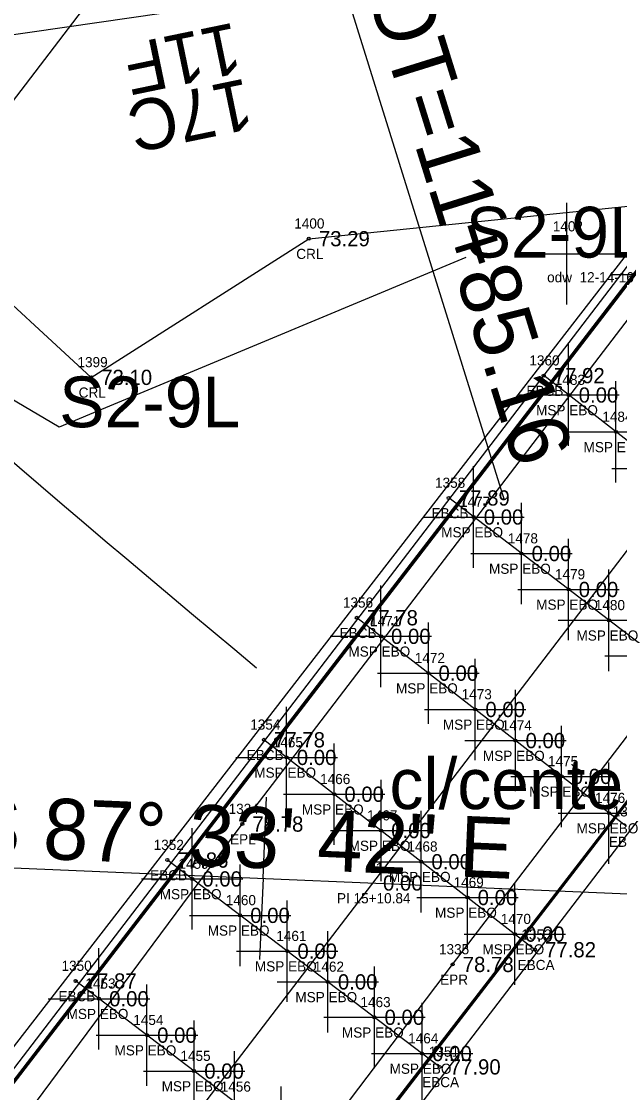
# Model space of a CAD drawing. Extents: x 2500794 to 2511032, y 910653 to 917533.
# Drawn here: x 2506040.7 to 2506099.6, y 913842.2 to 913947.8 of the extents above; entities that cross this region are included whole.
import ezdxf

# ---------------------------------------------------------------- set-up
doc = ezdxf.new("R2010")
doc.units = 0
for name, color, linetype in [('Default', 7, 'Continuous'), ('RD_EX_BldgApp', 7, 'Continuous'), ('RD_EX_Bridge', 7, 'Continuous'), ('RD_EX_Bridge_txCode', 7, 'Continuous'), ('RD_EX_GuardRail', 7, 'Continuous'), ('RD_EX_H2O', 7, 'Continuous'), ('RD_EX_H2O_txCode', 7, 'Continuous'), ('RD_EX_Misc', 7, 'Continuous'), ('RD_EX_Misc_txCode', 7, 'Continuous'), ('RD_EX_Road', 7, 'Continuous'), ('RD_EX_Road_txCode', 7, 'Continuous'), ('RD_EX_RW', 7, 'Continuous'), ('RD_EX_TX_Bridge_ELEV', 7, 'Continuous'), ('RD_EX_TX_H2O_ELEV', 7, 'Continuous'), ('RD_EX_TX_Misc_ELEV', 7, 'Continuous'), ('RD_EX_TX_Road_ELEV', 7, 'Continuous'), ('RD_EX_Wall', 7, 'Continuous'), ('RD_HC_Cl', 7, 'Continuous'), ('RD_HC_Data', 7, 'Continuous'), ('RD_HC_Data_Tic', 7, 'Continuous'), ('RD_HC_Survey_ELEV', 7, 'Continuous'), ('RD_HC_txCode', 7, 'Continuous'), ('RD_PD_Bridge', 7, 'Continuous'), ('RD_PD_Detour', 7, 'Continuous'), ('RD_PD_Signals', 7, 'Continuous'), ('RD_SMD_Locator', 7, 'Continuous')]:
    doc.layers.add(name, color=color, linetype=linetype)

# ---------------------------------------------------------------- blocks, each defined once
blk = doc.blocks.new('POINT_DISPLAY')
at = {"layer": 'Default'}
blk.add_line((0, 0), (0, 0), dxfattribs=at)
blk = doc.blocks.new('Non-Wetland Waters (Tributaries)')
at = {"layer": 'Default'}
blk.add_lwpolyline([(636545.457, 232136.839), (636535.278, 232132.59), (636524.99, 232138.661), (636521.558, 232134.094), (636513.303, 232133.696), (636494.497, 232132.445), (636478.322, 232133.569), (636463.424, 232143.109), (636451.693, 232146.366), (636448.31, 232143.99)], dxfattribs=at)

msp = doc.modelspace()

# ---------------------------------------------------------------- linework, layer by layer
at = {"layer": 'RD_EX_BldgApp'}
msp.add_line((2506016.51, 913816.53), (2506110.72, 913938.26), dxfattribs=at)
at = {"layer": 'RD_EX_Bridge'}
for p, q in [((2506118.69, 913892.22), (2506092.16, 913912.92)), ((2506109.65, 913880.37), (2506082.8, 913900.86)), ((2506100.31, 913868.46), (2506073.74, 913889.05)), ((2506091.3, 913856.32), (2506064.58, 913877.02)), ((2506081.9, 913844.77), (2506055.06, 913865.16)), ((2506072.88, 913832.83), (2506046.02, 913853.24))]:
    msp.add_line(p, q, dxfattribs=at)
for points in [[(2506044.21, 913797.79), (2506019.43, 913816.8), (2506111, 913935.92), (2506135.82, 913916.84), (2506044.21, 913797.79)], [(2506111.24, 913935.99), (2506135.76, 913916.92), (2506044.08, 913798.01), (2506019.65, 913816.86), (2506111.24, 913935.99)]]:
    msp.add_lwpolyline(points, dxfattribs=at)
at = {"layer": 'RD_EX_GuardRail'}
for p, q in [((2506019.73, 913816.87), (2506111.18, 913935.82)), ((2506044.2, 913797.96), (2506135.82, 913916.84))]:
    msp.add_line(p, q, dxfattribs=at)
at = {"layer": 'RD_EX_H2O_txCode'}
msp.add_lwpolyline([(2505808.2, 913925.07), (2505825.64, 913915.36), (2505914.54, 913915.98), (2505996.26, 913926.38), (2506005.4, 913936.74), (2506012.64, 913937.08), (2506022.61, 913935.73), (2506047.54, 913912.75), (2506069, 913926.42), (2506101.76, 913929.76), (2506134.82, 913911.49), (2506168.31, 913924.14), (2506205.52, 913926.29), (2506300.04, 913899.96), (2506387.24, 913834.45), (2506403.62, 913708.7), (2506351.33, 913635.45), (2506287.73, 913577.34)], dxfattribs=at)
at = {"layer": 'RD_EX_Misc'}
for p, q in [((2506094.44, 913919.94), (2506094.44, 913929.94)), ((2506089.44, 913924.94), (2506099.44, 913924.94)), ((2506098.84, 913922.89), (2506108.84, 913922.89)), ((2506094.61, 913906.01), (2506094.61, 913916.01)), ((2506099.28, 913902.37), (2506099.28, 913912.37)), ((2506089.61, 913911.01), (2506099.61, 913911.01)), ((2506094.28, 913907.37), (2506104.28, 913907.37)), ((2506085.25, 913893.98), (2506085.25, 913903.98)), ((2506098.89, 913903.77), (2506108.89, 913903.77)), ((2506089.97, 913890.38), (2506089.97, 913900.38)), ((2506080.25, 913898.98), (2506090.25, 913898.98)), ((2506094.61, 913886.84), (2506094.61, 913896.84)), ((2506084.97, 913895.38), (2506094.97, 913895.38)), ((2506098.59, 913883.8), (2506098.59, 913893.8)), ((2506076.11, 913882.22), (2506076.11, 913892.22)), ((2506089.61, 913891.84), (2506099.61, 913891.84)), ((2506080.79, 913878.59), (2506080.79, 913888.59)), ((2506093.59, 913888.8), (2506103.59, 913888.8)), ((2506071.11, 913887.22), (2506081.11, 913887.22)), ((2506085.41, 913875.01), (2506085.41, 913885.01)), ((2506098.18, 913885.3), (2506108.18, 913885.3)), ((2506075.79, 913883.59), (2506085.79, 913883.59)), ((2506089.37, 913871.94), (2506089.37, 913881.94)), ((2506066.82, 913870.28), (2506066.82, 913880.28)), ((2506080.41, 913880.01), (2506090.41, 913880.01)), ((2506093.93, 913868.41), (2506093.93, 913878.41)), ((2506071.51, 913866.65), (2506071.51, 913876.65)), ((2506084.37, 913876.94), (2506094.37, 913876.94)), ((2506061.82, 913875.28), (2506071.82, 913875.28)), ((2506098.59, 913864.79), (2506098.59, 913874.79)), ((2506088.93, 913873.41), (2506098.93, 913873.41)), ((2506076.13, 913863.07), (2506076.13, 913873.07)), ((2506066.51, 913871.65), (2506076.51, 913871.65)), ((2506080.09, 913860), (2506080.09, 913870)), ((2506093.59, 913869.79), (2506103.59, 913869.79)), ((2506057.51, 913858.3), (2506057.51, 913868.3)), ((2506071.13, 913868.07), (2506081.13, 913868.07)), ((2506084.65, 913856.47), (2506084.65, 913866.47)), ((2506075.09, 913865), (2506085.09, 913865)), ((2506062.23, 913854.71), (2506062.23, 913864.71)), ((2506052.51, 913863.3), (2506062.51, 913863.3)), ((2506089.32, 913852.86), (2506089.32, 913862.86)), ((2506066.88, 913851.18), (2506066.88, 913861.18)), ((2506079.65, 913861.47), (2506089.65, 913861.47)), ((2506057.23, 913859.71), (2506067.23, 913859.71)), ((2506070.87, 913848.15), (2506070.87, 913858.15)), ((2506084.32, 913857.86), (2506094.32, 913857.86)), ((2506048.32, 913846.49), (2506048.32, 913856.49)), ((2506061.88, 913856.18), (2506071.88, 913856.18)), ((2506075.47, 913844.66), (2506075.47, 913854.66)), ((2506065.87, 913853.15), (2506075.87, 913853.15)), ((2506053.05, 913842.9), (2506053.05, 913852.9)), ((2506043.32, 913851.49), (2506053.32, 913851.49)), ((2506080.17, 913841.09), (2506080.17, 913851.09)), ((2506057.7, 913839.36), (2506057.7, 913849.36)), ((2506070.47, 913849.66), (2506080.47, 913849.66)), ((2506048.05, 913847.9), (2506058.05, 913847.9)), ((2506061.69, 913836.33), (2506061.69, 913846.33)), ((2506075.17, 913846.09), (2506085.17, 913846.09)), ((2506052.7, 913844.36), (2506062.7, 913844.36)), ((2506066.28, 913832.84), (2506066.28, 913842.84))]:
    msp.add_line(p, q, dxfattribs=at)
at = {"layer": 'RD_EX_Road'}
for points in [[(2506022.41, 913814.76), (2506062.45, 913868.71), (2506112.78, 913934.56)], [(2506041.83, 913800.29), (2506083.18, 913854.87), (2506132.58, 913919.43)]]:
    msp.add_lwpolyline(points, dxfattribs=at)
at = {"layer": 'RD_EX_RW'}
msp.add_line((2505954.67, 913828.58), (2506112.58, 914035.13), dxfattribs=at)
at = {"layer": 'RD_EX_Wall'}
msp.add_arc((2507719.02, 915869.8), 2585.05, 222.30098, 230.18686, dxfattribs=at)
at = {"layer": 'RD_HC_Cl'}
for p, q in [((2505807.57, 913512.69), (2506748.89, 914743.92)), ((2505870.76, 913871.61), (2506259.06, 913855.07))]:
    msp.add_line(p, q, dxfattribs=at)
at = {"layer": 'RD_HC_Data'}
msp.add_line((2506051.85, 914017.46), (2506088.25, 913900.68), dxfattribs=at)
at = {"layer": 'RD_HC_Data_Tic'}
for q in [(2506064.83, 913871.35), (2506064.15, 913855.37)]:
    msp.add_line((2506064.49, 913863.36), q, dxfattribs=at)
at = {"layer": 'RD_PD_Bridge'}
for p, q in [((2506007.09, 913801.65), (2506128.56, 913960.53)), ((2506034.1, 913781), (2506155.57, 913939.88))]:
    msp.add_line(p, q, dxfattribs=at)
at = {"layer": 'RD_PD_Signals'}
msp.add_line((2506061.31, 913949.6), (2506006.44, 913941.72), dxfattribs=at)
at = {"layer": 'RD_SMD_Locator'}
for centre in [(2506069, 913926.42), (2506047.54, 913912.75), (2506092.16, 913912.92), (2506094.61, 913911.01), (2506099.28, 913907.37), (2506082.8, 913900.86), (2506085.25, 913898.98), (2506089.97, 913895.38), (2506094.61, 913891.84), (2506073.74, 913889.05), (2506098.59, 913888.8), (2506076.11, 913887.22), (2506080.79, 913883.59), (2506085.41, 913880.01), (2506064.58, 913877.02), (2506089.37, 913876.94), (2506066.82, 913875.28), (2506093.93, 913873.41), (2506071.51, 913871.65), (2506098.59, 913869.79), (2506062.45, 913868.71), (2506076.13, 913868.07), (2506055.06, 913865.16), (2506080.09, 913865), (2506057.51, 913863.3), (2506084.65, 913861.47), (2506062.23, 913859.71), (2506089.32, 913857.86), (2506066.88, 913856.18), (2506091.3, 913856.32), (2506083.18, 913854.87), (2506046.02, 913853.24), (2506070.87, 913853.15), (2506048.32, 913851.49), (2506075.47, 913849.66), (2506053.05, 913847.9), (2506080.17, 913846.09), (2506081.9, 913844.77), (2506057.7, 913844.36)]:
    msp.add_circle(centre, 0.15, dxfattribs=at)

# ---------------------------------------------------------------- block references
at = {"layer": 'Default', "xscale": 3.937007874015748, "yscale": 3.937007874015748}
for name, p in [('Non-Wetland Waters (Tributaries)', (0, 0)), ('POINT_DISPLAY', (2506084.48, 913924.56)), ('POINT_DISPLAY', (2506084.48, 913924.56)), ('POINT_DISPLAY', (2506044.4, 913907.83)), ('POINT_DISPLAY', (2506044.4, 913907.83)), ('POINT_DISPLAY', (2506076.96, 913870.19)), ('POINT_DISPLAY', (2506076.96, 913870.19))]:
    msp.add_blockref(name, p, dxfattribs=at)
at = {"layer": 'RD_EX_H2O', "xscale": 3.937007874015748, "yscale": 3.937007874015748}
msp.add_blockref('Non-Wetland Waters (Tributaries)', (0, 0), dxfattribs=at)

# ---------------------------------------------------------------- texts
at = {"layer": 'Default'}
for s, p in [('S2-9L BRIDGE', (2506084.48, 913924.56)), ('S2-9L BRIDGE', (2506084.48, 913924.56)), ('S2-9L', (2506044.4, 913907.83)), ('S2-9L', (2506044.4, 913907.83)), ('cl/center bridge', (2506076.96, 913870.19)), ('cl/center bridge', (2506076.96, 913870.19))]:
    msp.add_text(s, height=5, dxfattribs=at).set_placement(p)
at = {"layer": 'RD_EX_Bridge_txCode'}
for s, p in [('1360', (2506090.75, 913913.92)), ('EBCB', (2506090.46, 913910.92)), ('1358', (2506081.45, 913901.86)), ('EBCB', (2506081.1, 913898.86)), ('1356', (2506072.37, 913890.05)), ('EBCB', (2506072.04, 913887.05)), ('1354', (2506063.23, 913878.02)), ('EBCB', (2506062.88, 913875.02)), ('1355', (2506098.96, 913869.46)), ('1352', (2506053.71, 913866.16)), ('EBCA', (2506098.59, 913866.46)), ('EBCB', (2506053.36, 913863.16)), ('1353', (2506089.96, 913857.32)), ('1350', (2506044.63, 913854.24)), ('EBCA', (2506089.59, 913854.32)), ('EBCB', (2506044.32, 913851.24)), ('1351', (2506080.84, 913845.77)), ('EBCA', (2506080.18, 913842.77))]:
    msp.add_text(s, height=1, dxfattribs=at).set_placement(p)
at = {"layer": 'RD_EX_H2O_txCode'}
for s, p in [('1400', (2506067.57, 913927.42)), ('1402', (2506093.06, 913927.14)), ('CRL', (2506067.77, 913924.42)), ('odw  12-14-16', (2506092.5, 913922.12)), ('1399', (2506046.2, 913913.75)), ('CRL', (2506046.32, 913910.75))]:
    msp.add_text(s, height=1, dxfattribs=at).set_placement(p)
at = {"layer": 'RD_EX_Misc_txCode'}
for s, p in [('1483', (2506093.26, 913912.01)), ('MSP EBO', (2506091.41, 913909.01)), ('1484', (2506097.94, 913908.37)), ('MSP EBO', (2506096.09, 913905.37)), ('1477', (2506083.91, 913899.98)), ('MSP EBO', (2506082.06, 913896.98)), ('1478', (2506088.62, 913896.38)), ('MSP EBO', (2506086.77, 913893.38)), ('1479', (2506093.27, 913892.84)), ('MSP EBO', (2506091.42, 913889.84)), ('1480', (2506097.2, 913889.8)), ('1471', (2506075.04, 913888.22)), ('MSP EBO', (2506095.39, 913886.8)), ('MSP EBO', (2506072.91, 913885.22)), ('1472', (2506079.45, 913884.59)), ('MSP EBO', (2506077.6, 913881.59)), ('1473', (2506084.07, 913881.01)), ('MSP EBO', (2506082.22, 913878.01)), ('1474', (2506088.02, 913877.94)), ('1465', (2506065.45, 913876.28)), ('MSP EBO', (2506086.17, 913874.94)), ('1475', (2506092.58, 913874.41)), ('MSP EBO', (2506063.63, 913873.28)), ('1466', (2506070.12, 913872.65)), ('MSP EBO', (2506090.73, 913871.41)), ('1476', (2506097.22, 913870.79)), ('MSP EBO', (2506068.32, 913869.65)), ('1467', (2506074.76, 913869.07)), ('MSP EBO', (2506095.4, 913867.79)), ('MSP EBO', (2506072.93, 913866.07)), ('1468', (2506078.72, 913866)), ('1459', (2506056.16, 913864.3)), ('MSP EBO', (2506076.89, 913863)), ('1469', (2506083.28, 913862.47)), ('MSP EBO', (2506054.31, 913861.3)), ('1460', (2506060.82, 913860.71)), ('MSP EBO', (2506081.45, 913859.47)), ('1470', (2506087.93, 913858.86)), ('MSP EBO', (2506059.04, 913857.71)), ('1461', (2506065.8, 913857.18)), ('MSP EBO', (2506086.12, 913855.86)), ('MSP EBO', (2506063.69, 913854.18)), ('1462', (2506069.5, 913854.15)), ('1453', (2506046.98, 913852.49)), ('MSP EBO', (2506067.68, 913851.15)), ('1463', (2506074.1, 913850.66)), ('MSP EBO', (2506045.13, 913849.49)), ('1454', (2506051.7, 913848.9)), ('MSP EBO', (2506072.27, 913847.66)), ('1464', (2506078.8, 913847.09)), ('MSP EBO', (2506049.85, 913845.9)), ('1455', (2506056.35, 913845.36)), ('MSP EBO', (2506076.97, 913844.09)), ('MSP EBO', (2506054.5, 913842.36)), ('1456', (2506060.32, 913842.33))]:
    msp.add_text(s, height=1, dxfattribs=at).set_placement(p)
at = {"layer": 'RD_EX_Road_txCode'}
for s, p in [('1334', (2506061.1, 913869.71)), ('EPL', (2506061.24, 913866.71)), ('1335', (2506081.84, 913855.87)), ('EPR', (2506081.95, 913852.87))]:
    msp.add_text(s, height=1, dxfattribs=at).set_placement(p)
at = {"layer": 'RD_EX_TX_Bridge_ELEV'}
for s, p in [('77.92', (2506093.16, 913912.17)), ('77.89', (2506083.8, 913900.11)), ('77.78', (2506074.74, 913888.3)), ('77.78', (2506065.58, 913876.27)), ('77.86', (2506056.06, 913864.41)), ('77.82', (2506092.3, 913855.57)), ('77.87', (2506047.02, 913852.49)), ('77.90', (2506082.9, 913844.02))]:
    msp.add_text(s, height=1.5, dxfattribs=at).set_placement(p)
at = {"layer": 'RD_EX_TX_H2O_ELEV'}
for s, p in [('73.29', (2506070, 913925.67)), ('73.10', (2506048.54, 913912))]:
    msp.add_text(s, height=1.5, dxfattribs=at).set_placement(p)
at = {"layer": 'RD_EX_TX_Misc_ELEV'}
for p in [(2506095.61, 913910.26), (2506086.25, 913898.23), (2506090.97, 913894.63), (2506095.61, 913891.09), (2506077.11, 913886.47), (2506081.79, 913882.84), (2506086.41, 913879.26), (2506090.37, 913876.19), (2506067.82, 913874.53), (2506094.93, 913872.66), (2506072.51, 913870.9), (2506077.13, 913867.32), (2506081.09, 913864.25), (2506058.51, 913862.55), (2506085.65, 913860.72), (2506063.23, 913858.96), (2506090.32, 913857.11), (2506067.88, 913855.43), (2506071.87, 913852.4), (2506049.32, 913850.74), (2506076.47, 913848.91), (2506054.05, 913847.15), (2506081.17, 913845.34), (2506058.7, 913843.61)]:
    msp.add_text('0.00', height=1.5, dxfattribs=at).set_placement(p)
at = {"layer": 'RD_EX_TX_Road_ELEV'}
for p in [(2506063.45, 913867.96), (2506084.18, 913854.12)]:
    msp.add_text('78.78', height=1.5, dxfattribs=at).set_placement(p)
at = {"layer": 'RD_HC_Data'}
for s, rotation, p in [('POT=11+85.16', 287.3108, (2506073.1, 913956)), ('S 87%%d 33\' 42" E', 357.5616, (2506035.15, 913865.61))]:
    msp.add_text(s, height=6, rotation=rotation, dxfattribs=at).set_placement(p)
at = {"layer": 'RD_HC_Survey_ELEV'}
msp.add_text('0.00', height=1.5, dxfattribs=at).set_placement((2506076.32, 913862.15))
at = {"layer": 'RD_HC_txCode'}
for s, p in [('31', (2506074.87, 913863.9)), ('PI 15+10.84', (2506071.78, 913860.9))]:
    msp.add_text(s, height=1, dxfattribs=at).set_placement(p)
at = {"layer": 'RD_PD_Detour'}
msp.add_text('11F', height=5, rotation=191.6795, dxfattribs=at).set_placement((2506061.69, 913947.76))
at = {"layer": 'RD_PD_Signals'}
msp.add_text('17C', height=5, rotation=191.6795, dxfattribs=at).set_placement((2506062.83, 913942.25))

doc.saveas('drawing.dxf')
